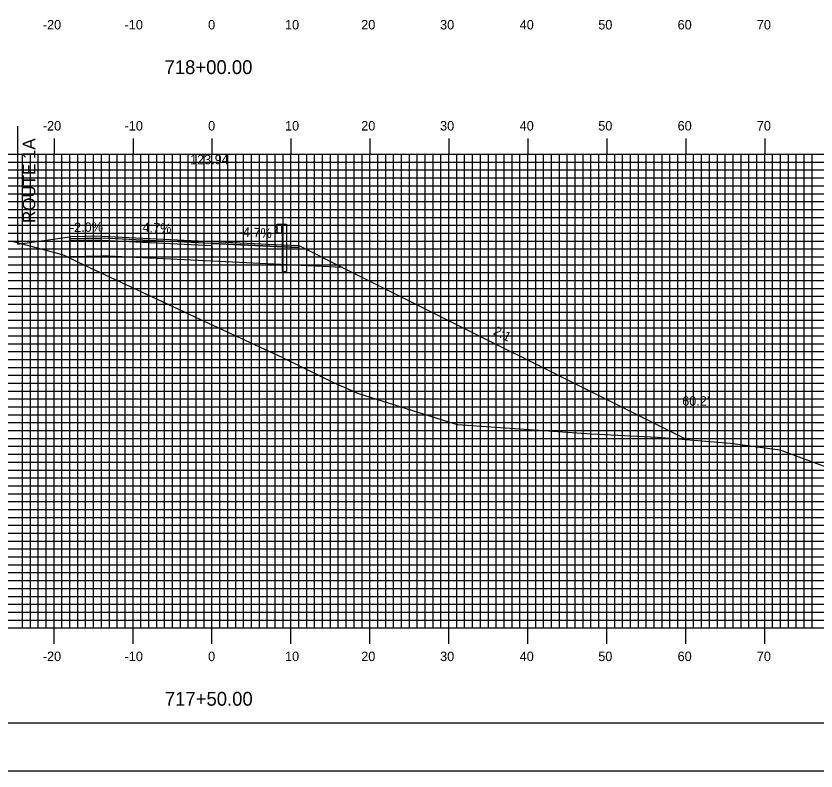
# Model space of a CAD drawing. Extents: x 857265 to 857608, y 364366 to 364586.
# Drawn here: x 857405.5 to 857506.8, y 364365.7 to 364461.3 of the extents above; entities that cross this region are included whole.
import ezdxf

# ---------------------------------------------------------------- set-up
doc = ezdxf.new("R2010")
doc.units = 0
for name, color, linetype in [('ANNOTATION', 7, 'Continuous'), ('BORDER', 7, 'Continuous'), ('D_Guardrail_Beam_Rt', 7, 'Continuous'), ('D_Roadway_Centerline_Text', 7, 'Continuous'), ('D_Roadway_Edge_Shoulder', 7, 'Continuous'), ('D_Roadway_Edge_TW', 7, 'Continuous'), ('D_Roadway_Pavement', 7, 'Continuous'), ('D_Roadway_SlopeLines', 7, 'Continuous'), ('D_Roadway_SubGrade', 7, 'Continuous'), ('D_Text_Standard', 7, 'Continuous'), ('H_V ANNOTATION', 7, 'Continuous'), ('MAJOR', 7, 'Continuous'), ('MINOR', 7, 'Continuous'), ('PLOT BOUNDARY', 7, 'Continuous'), ('S_Roadway_Centerline', 7, 'Continuous')]:
    doc.layers.add(name, color=color, linetype=linetype)

msp = doc.modelspace()

# ---------------------------------------------------------------- linework, layer by layer
at = {"layer": 'BORDER'}
msp.add_lwpolyline([(857280.74, 364371.79), (857600.74, 364371.79), (857600.74, 364581.79), (857280.74, 364581.79)], close=True, dxfattribs=at)
at = {"layer": 'D_Guardrail_Beam_Rt'}
for p, q in [((857438.52, 364434.83), (857438.37, 364434.73)), ((857438.37, 364434.59), (857438.57, 364434.45)), ((857438.61, 364434.85), (857438.53, 364434.84)), ((857438.61, 364434.94), (857439.29, 364434.94)), ((857438.61, 364433.77), (857438.61, 364434.94)), ((857439.13, 364434.94), (857439.13, 364433.77)), ((857439.23, 364434.94), (857439.23, 364433.77)), ((857439.29, 364434.94), (857439.76, 364434.94)), ((857439.29, 364434.94), (857439.29, 364433.77)), ((857439.76, 364434.94), (857439.76, 364428.94)), ((857438.57, 364434.25), (857438.37, 364434.12)), ((857438.37, 364433.97), (857438.52, 364433.87)), ((857438.53, 364433.87), (857438.61, 364433.85)), ((857438.6, 364434.39), (857438.6, 364434.32)), ((857439.29, 364433.77), (857438.61, 364433.77)), ((857439.27, 364428.94), (857439.27, 364433.77)), ((857439.27, 364428.94), (857439.76, 364428.94))]:
    msp.add_line(p, q, dxfattribs=at)
for centre, major_axis, start_param, end_param in [((857438.42, 364434.66), (-0.0877, 0), 5.323254, 7.243116), ((857438.54, 364434.8), (-0.0417, 0), 4.907132, 5.323254), ((857438.52, 364434.39), (0.0789, 0), 0, 0.959931), ((857438.42, 364434.05), (-0.0877, 0), 5.323254, 7.243116), ((857438.54, 364433.91), (-0.0417, 0), 0.959931, 1.376053), ((857438.52, 364434.32), (0.0789, 0), 5.323254, 6.283185)]:
    msp.add_ellipse(centre, major_axis=major_axis, ratio=0.995501, start_param=start_param, end_param=end_param, dxfattribs=at)
at = {"layer": 'D_Roadway_Edge_Shoulder'}
for points in [[(857416.34, 364433.4), (857412.34, 364433.32), (857412.34, 364433.07), (857416.34, 364433.15)], [(857430.34, 364432.73), (857438.34, 364432.35), (857438.34, 364432.35), (857441.34, 364432.21), (857441.34, 364431.96), (857430.34, 364432.48)]]:
    msp.add_lwpolyline(points, close=True, dxfattribs=at)
at = {"layer": 'D_Roadway_Edge_TW'}
msp.add_lwpolyline([(857416.34, 364433.4), (857430.34, 364432.73), (857430.34, 364432.48), (857416.34, 364433.15)], close=True, dxfattribs=at)
at = {"layer": 'D_Roadway_Pavement'}
msp.add_lwpolyline([(857416.34, 364433.15), (857412.34, 364433.07), (857412.34, 364432.82), (857416.34, 364432.9)], close=True, dxfattribs=at)
at = {"layer": 'D_Roadway_SlopeLines'}
for p, q in [((857405.7, 364432.4), (857412.34, 364433.32)), ((857446.86, 364429.45), (857490.49, 364407.65))]:
    msp.add_line(p, q, dxfattribs=at)
at = {"layer": 'D_Roadway_SubGrade'}
msp.add_line((857405.7, 364447.35), (857405.7, 364432.4), dxfattribs=at)
for points in [[(857416.34, 364432.9), (857412.34, 364432.82), (857412.34, 364433.07), (857412.34, 364433.32), (857412.34, 364430.82), (857416.34, 364430.9)], [(857416.34, 364432.9), (857430.34, 364432.23), (857430.34, 364430.23), (857416.34, 364430.9)], [(857430.34, 364432.23), (857430.34, 364432.48), (857441.34, 364431.96), (857441.34, 364432.21), (857446.86, 364429.45), (857430.34, 364430.23)]]:
    msp.add_lwpolyline(points, close=True, dxfattribs=at)
at = {"layer": 'MAJOR'}
for p, q in [((857410.34, 364445.79), (857410.34, 364443.79)), ((857420.34, 364445.79), (857420.34, 364443.79)), ((857430.34, 364445.79), (857430.34, 364443.79)), ((857440.34, 364445.79), (857440.34, 364443.79)), ((857450.34, 364445.79), (857450.34, 364443.79)), ((857460.34, 364445.79), (857460.34, 364443.79)), ((857470.34, 364445.79), (857470.34, 364443.79)), ((857480.34, 364445.79), (857480.34, 364443.79)), ((857490.34, 364445.79), (857490.34, 364443.79)), ((857500.34, 364445.79), (857500.34, 364443.79)), ((857290.34, 364443.79), (857570.34, 364443.79)), ((857290.34, 364443.79), (857570.34, 364443.79)), ((857410.34, 364383.79), (857410.34, 364443.79)), ((857420.34, 364383.79), (857420.34, 364443.79)), ((857430.34, 364383.79), (857430.34, 364443.79)), ((857440.34, 364383.79), (857440.34, 364443.79)), ((857450.34, 364383.79), (857450.34, 364443.79)), ((857460.34, 364383.79), (857460.34, 364443.79)), ((857470.34, 364383.79), (857470.34, 364443.79)), ((857480.34, 364383.79), (857480.34, 364443.79)), ((857490.34, 364383.79), (857490.34, 364443.79)), ((857500.34, 364383.79), (857500.34, 364443.79)), ((857290.34, 364438.79), (857570.34, 364438.79)), ((857290.34, 364433.79), (857570.34, 364433.79)), ((857290.34, 364428.79), (857570.34, 364428.79)), ((857290.34, 364423.79), (857570.34, 364423.79)), ((857290.34, 364418.79), (857570.34, 364418.79)), ((857290.34, 364413.79), (857570.34, 364413.79)), ((857290.34, 364408.79), (857570.34, 364408.79)), ((857290.34, 364403.79), (857570.34, 364403.79)), ((857290.34, 364398.79), (857570.34, 364398.79)), ((857290.34, 364393.79), (857570.34, 364393.79)), ((857290.34, 364388.79), (857570.34, 364388.79)), ((857290.34, 364383.79), (857570.34, 364383.79)), ((857290.34, 364383.79), (857570.34, 364383.79)), ((857410.34, 364381.78), (857410.34, 364383.79)), ((857420.34, 364381.78), (857420.34, 364383.79)), ((857430.34, 364381.78), (857430.34, 364383.79)), ((857440.34, 364381.78), (857440.34, 364383.79)), ((857450.34, 364381.78), (857450.34, 364383.79)), ((857460.34, 364381.78), (857460.34, 364383.79)), ((857470.34, 364381.78), (857470.34, 364383.79)), ((857480.34, 364381.78), (857480.34, 364383.79)), ((857490.34, 364381.78), (857490.34, 364383.79)), ((857500.34, 364381.78), (857500.34, 364383.79))]:
    msp.add_line(p, q, dxfattribs=at)
at = {"layer": 'MINOR'}
for p, q in [((857406.34, 364383.79), (857406.34, 364443.79)), ((857407.34, 364383.79), (857407.34, 364443.79)), ((857408.34, 364383.79), (857408.34, 364443.79)), ((857409.34, 364383.79), (857409.34, 364443.79)), ((857411.34, 364383.79), (857411.34, 364443.79)), ((857412.34, 364383.79), (857412.34, 364443.79)), ((857413.34, 364383.79), (857413.34, 364443.79)), ((857414.34, 364383.79), (857414.34, 364443.79)), ((857415.34, 364383.79), (857415.34, 364443.79)), ((857416.34, 364383.79), (857416.34, 364443.79)), ((857417.34, 364383.79), (857417.34, 364443.79)), ((857418.34, 364383.79), (857418.34, 364443.79)), ((857419.34, 364383.79), (857419.34, 364443.79)), ((857421.34, 364383.79), (857421.34, 364443.79)), ((857422.34, 364383.79), (857422.34, 364443.79)), ((857423.34, 364383.79), (857423.34, 364443.79)), ((857424.34, 364383.79), (857424.34, 364443.79)), ((857425.34, 364383.79), (857425.34, 364443.79)), ((857426.34, 364383.79), (857426.34, 364443.79)), ((857427.34, 364383.79), (857427.34, 364443.79)), ((857428.34, 364383.79), (857428.34, 364443.79)), ((857429.34, 364383.79), (857429.34, 364443.79)), ((857431.34, 364383.79), (857431.34, 364443.79)), ((857432.34, 364383.79), (857432.34, 364443.79)), ((857433.34, 364383.79), (857433.34, 364443.79)), ((857434.34, 364383.79), (857434.34, 364443.79)), ((857435.34, 364383.79), (857435.34, 364443.79)), ((857436.34, 364383.79), (857436.34, 364443.79)), ((857437.34, 364383.79), (857437.34, 364443.79)), ((857438.34, 364383.79), (857438.34, 364443.79)), ((857439.34, 364383.79), (857439.34, 364443.79)), ((857441.34, 364383.79), (857441.34, 364443.79)), ((857442.34, 364383.79), (857442.34, 364443.79)), ((857443.34, 364383.79), (857443.34, 364443.79)), ((857444.34, 364383.79), (857444.34, 364443.79)), ((857445.34, 364383.79), (857445.34, 364443.79)), ((857446.34, 364383.79), (857446.34, 364443.79)), ((857447.34, 364383.79), (857447.34, 364443.79)), ((857448.34, 364383.79), (857448.34, 364443.79)), ((857449.34, 364383.79), (857449.34, 364443.79)), ((857451.34, 364383.79), (857451.34, 364443.79)), ((857452.34, 364383.79), (857452.34, 364443.79)), ((857453.34, 364383.79), (857453.34, 364443.79)), ((857454.34, 364383.79), (857454.34, 364443.79)), ((857455.34, 364383.79), (857455.34, 364443.79)), ((857456.34, 364383.79), (857456.34, 364443.79)), ((857457.34, 364383.79), (857457.34, 364443.79)), ((857458.34, 364383.79), (857458.34, 364443.79)), ((857459.34, 364383.79), (857459.34, 364443.79)), ((857461.34, 364383.79), (857461.34, 364443.79)), ((857462.34, 364383.79), (857462.34, 364443.79)), ((857463.34, 364383.79), (857463.34, 364443.79)), ((857464.34, 364383.79), (857464.34, 364443.79)), ((857465.34, 364383.79), (857465.34, 364443.79)), ((857466.34, 364383.79), (857466.34, 364443.79)), ((857467.34, 364383.79), (857467.34, 364443.79)), ((857468.34, 364383.79), (857468.34, 364443.79)), ((857469.34, 364383.79), (857469.34, 364443.79)), ((857471.34, 364383.79), (857471.34, 364443.79)), ((857472.34, 364383.79), (857472.34, 364443.79)), ((857473.34, 364383.79), (857473.34, 364443.79)), ((857474.34, 364383.79), (857474.34, 364443.79)), ((857475.34, 364383.79), (857475.34, 364443.79)), ((857476.34, 364383.79), (857476.34, 364443.79)), ((857477.34, 364383.79), (857477.34, 364443.79)), ((857478.34, 364383.79), (857478.34, 364443.79)), ((857479.34, 364383.79), (857479.34, 364443.79)), ((857481.34, 364383.79), (857481.34, 364443.79)), ((857482.34, 364383.79), (857482.34, 364443.79)), ((857483.34, 364383.79), (857483.34, 364443.79)), ((857484.34, 364383.79), (857484.34, 364443.79)), ((857485.34, 364383.79), (857485.34, 364443.79)), ((857486.34, 364383.79), (857486.34, 364443.79)), ((857487.34, 364383.79), (857487.34, 364443.79)), ((857488.34, 364383.79), (857488.34, 364443.79)), ((857489.34, 364383.79), (857489.34, 364443.79)), ((857491.34, 364383.79), (857491.34, 364443.79)), ((857492.34, 364383.79), (857492.34, 364443.79)), ((857493.34, 364383.79), (857493.34, 364443.79)), ((857494.34, 364383.79), (857494.34, 364443.79)), ((857495.34, 364383.79), (857495.34, 364443.79)), ((857496.34, 364383.79), (857496.34, 364443.79)), ((857497.34, 364383.79), (857497.34, 364443.79)), ((857498.34, 364383.79), (857498.34, 364443.79)), ((857499.34, 364383.79), (857499.34, 364443.79)), ((857501.34, 364383.79), (857501.34, 364443.79)), ((857502.34, 364383.79), (857502.34, 364443.79)), ((857503.34, 364383.79), (857503.34, 364443.79)), ((857504.34, 364383.79), (857504.34, 364443.79)), ((857505.34, 364383.79), (857505.34, 364443.79)), ((857506.34, 364383.79), (857506.34, 364443.79)), ((857290.34, 364442.79), (857570.34, 364442.79)), ((857290.34, 364441.79), (857570.34, 364441.79)), ((857290.34, 364440.79), (857570.34, 364440.79)), ((857290.34, 364439.79), (857570.34, 364439.79)), ((857290.34, 364437.79), (857570.34, 364437.79)), ((857290.34, 364436.79), (857570.34, 364436.79)), ((857290.34, 364435.79), (857570.34, 364435.79)), ((857290.34, 364434.79), (857570.34, 364434.79)), ((857290.34, 364432.79), (857570.34, 364432.79)), ((857290.34, 364431.79), (857570.34, 364431.79)), ((857290.34, 364430.79), (857570.34, 364430.79)), ((857290.34, 364429.79), (857570.34, 364429.79)), ((857290.34, 364427.79), (857570.34, 364427.79)), ((857290.34, 364426.79), (857570.34, 364426.79)), ((857290.34, 364425.79), (857570.34, 364425.79)), ((857290.34, 364424.79), (857570.34, 364424.79)), ((857290.34, 364422.79), (857570.34, 364422.79)), ((857290.34, 364421.79), (857570.34, 364421.79)), ((857290.34, 364420.79), (857570.34, 364420.79)), ((857290.34, 364419.79), (857570.34, 364419.79)), ((857290.34, 364417.79), (857570.34, 364417.79)), ((857290.34, 364416.79), (857570.34, 364416.79)), ((857290.34, 364415.79), (857570.34, 364415.79)), ((857290.34, 364414.79), (857570.34, 364414.79)), ((857290.34, 364412.79), (857570.34, 364412.79)), ((857290.34, 364411.79), (857570.34, 364411.79)), ((857290.34, 364410.79), (857570.34, 364410.79)), ((857290.34, 364409.79), (857570.34, 364409.79)), ((857290.34, 364407.79), (857570.34, 364407.79)), ((857290.34, 364406.79), (857570.34, 364406.79)), ((857290.34, 364405.79), (857570.34, 364405.79)), ((857290.34, 364404.79), (857570.34, 364404.79)), ((857290.34, 364402.79), (857570.34, 364402.79)), ((857290.34, 364401.79), (857570.34, 364401.79)), ((857290.34, 364400.79), (857570.34, 364400.79)), ((857290.34, 364399.79), (857570.34, 364399.79)), ((857290.34, 364397.79), (857570.34, 364397.79)), ((857290.34, 364396.79), (857570.34, 364396.79)), ((857290.34, 364395.79), (857570.34, 364395.79)), ((857290.34, 364394.79), (857570.34, 364394.79)), ((857290.34, 364392.79), (857570.34, 364392.79)), ((857290.34, 364391.79), (857570.34, 364391.79)), ((857290.34, 364390.79), (857570.34, 364390.79)), ((857290.34, 364389.79), (857570.34, 364389.79)), ((857290.34, 364387.79), (857570.34, 364387.79)), ((857290.34, 364386.79), (857570.34, 364386.79)), ((857290.34, 364385.79), (857570.34, 364385.79)), ((857290.34, 364384.79), (857570.34, 364384.79))]:
    msp.add_line(p, q, dxfattribs=at)
at = {"layer": 'PLOT BOUNDARY'}
msp.add_lwpolyline([(857264.55, 364365.67), (857604.55, 364365.67), (857604.55, 364585.67), (857264.55, 364585.67)], close=True, dxfattribs=at)
at = {"layer": 'S_Roadway_Centerline'}
msp.add_lwpolyline([(857404.88, 364432.81), (857411.36, 364431.08), (857411.78, 364430.91), (857413.4, 364430.11), (857428.18, 364423.21), (857439.25, 364418.03), (857445.73, 364414.89), (857448.9, 364413.49), (857460.95, 364409.69), (857461.3, 364409.58), (857461.44, 364409.57), (857478.38, 364408.37), (857486.77, 364407.96), (857495.98, 364407.19), (857502.27, 364406.36), (857523.41, 364398.52), (857530.98, 364395.44), (857540.32, 364391.98), (857551.23, 364390.63), (857553.46, 364390.3), (857568.3, 364389.73), (857569.71, 364389.72), (857570.34, 364389.72)], dxfattribs=at)

# ---------------------------------------------------------------- texts
at = {"layer": 'ANNOTATION'}
for s, height, rotation, p in [('ROUTE 1A', 1.6, 90, (857407.96, 364435.09)), ('-2.0%', 1.2, 1.1458, (857412.35, 364433.91)), ('4.7%', 1.2, 357.2868, (857421.52, 364433.95)), ('-4.7%', 1.2, 357.2868, (857433.7, 364433.37)), ('2:1', 1.2, 333.4349, (857465.85, 364421.01))]:
    msp.add_text(s, height=height, rotation=rotation, dxfattribs=at).set_placement(p)
at = {"layer": 'D_Roadway_Centerline_Text'}
msp.add_text('123.94', height=1.2, dxfattribs=at).set_placement((857427.56, 364442.52))
at = {"layer": 'D_Text_Standard'}
msp.add_text("60.2'", height=1.2, dxfattribs=at).set_placement((857489.89, 364411.94))
at = {"layer": 'H_V ANNOTATION'}
for s, height, p in [('-20', 1.2, (857408.92, 364459.59)), ('-10', 1.2, (857419.27, 364459.59)), ('0', 1.2, (857429.85, 364459.59)), ('10', 1.2, (857439.59, 364459.59)), ('20', 1.2, (857449.24, 364459.59)), ('30', 1.2, (857459.23, 364459.59)), ('40', 1.2, (857469.31, 364459.59)), ('50', 1.2, (857479.26, 364459.59)), ('60', 1.2, (857489.31, 364459.59)), ('70', 1.2, (857499.34, 364459.59)), ('718+00.00', 1.75, (857424.33, 364453.94)), ('-20', 1.2, (857408.92, 364446.79)), ('-10', 1.2, (857419.27, 364446.79)), ('0', 1.2, (857429.85, 364446.79)), ('10', 1.2, (857439.59, 364446.79)), ('20', 1.2, (857449.24, 364446.79)), ('30', 1.2, (857459.23, 364446.79)), ('40', 1.2, (857469.31, 364446.79)), ('50', 1.2, (857479.26, 364446.79)), ('60', 1.2, (857489.31, 364446.79)), ('70', 1.2, (857499.34, 364446.79)), ('-20', 1.2, (857408.92, 364379.59)), ('-10', 1.2, (857419.27, 364379.59)), ('0', 1.2, (857429.85, 364379.59)), ('10', 1.2, (857439.59, 364379.59)), ('20', 1.2, (857449.24, 364379.59)), ('30', 1.2, (857459.23, 364379.59)), ('40', 1.2, (857469.31, 364379.59)), ('50', 1.2, (857479.26, 364379.59)), ('60', 1.2, (857489.31, 364379.59)), ('70', 1.2, (857499.34, 364379.59)), ('717+50.00', 1.75, (857424.37, 364373.94))]:
    msp.add_text(s, height=height, dxfattribs=at).set_placement(p)

doc.saveas('drawing.dxf')
